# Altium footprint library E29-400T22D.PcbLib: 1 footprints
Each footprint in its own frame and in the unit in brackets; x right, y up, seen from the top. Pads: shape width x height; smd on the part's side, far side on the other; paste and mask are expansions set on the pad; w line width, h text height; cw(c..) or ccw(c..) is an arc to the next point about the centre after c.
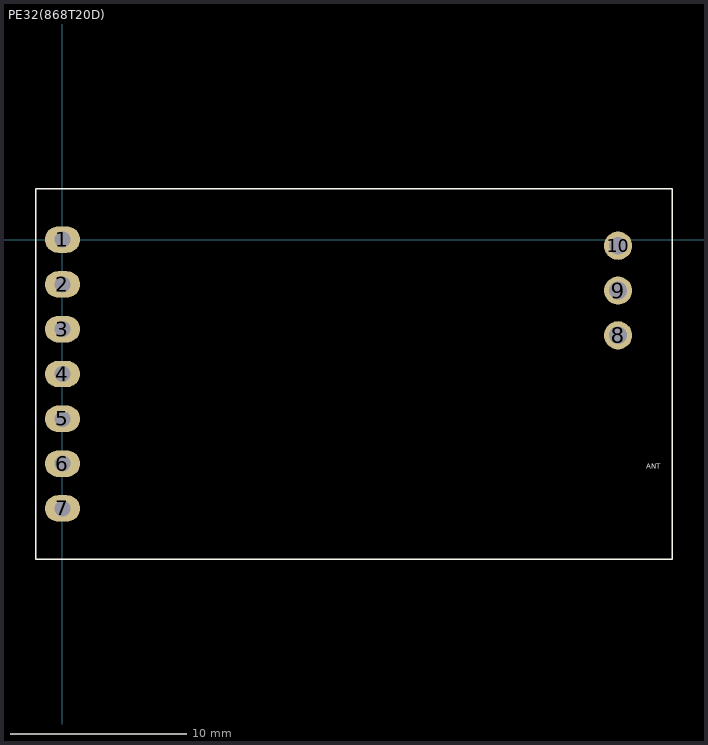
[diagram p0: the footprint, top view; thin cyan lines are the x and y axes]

## PE32(868T20D) [mm] "36mm*21mm-D/SMA长度12.5mm"
height 7.2
pads (10):
  oval 2x1.5 hole 0.9: 1(0,0) 2(0,-2.54) 3(0,-5.08) 4(0,-7.62) 5(0,-10.16) 6(0,-12.7) 7(0,-15.24)
  round 1.6 hole 1: 8(31.49,-5.43) 9(31.49,-2.89) 10(31.49,-0.35)
Top Overlay:
  lines w0.1: -1.51,-18.12 -1.51,2.88 34.558,2.88 34.558,-18.12 -1.51,-18.12
  text "ANT" at 33.079,-13.092 h0.5
Bottom Overlay:
  text "TXD" at 4.5,-8.113 h1.5
  text "M0" at 4.5,-0.454 h1.5
  text "M1" at 4.5,-3.042 h1.5
  text "RXD" at 4.5,-5.538 h1.5
  text "AUX" at 4.5,-10.608 h1.5
  text "VCC" at 4.5,-13.329 h1.5
  text "GND" at 4.5,-15.754 h1.5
